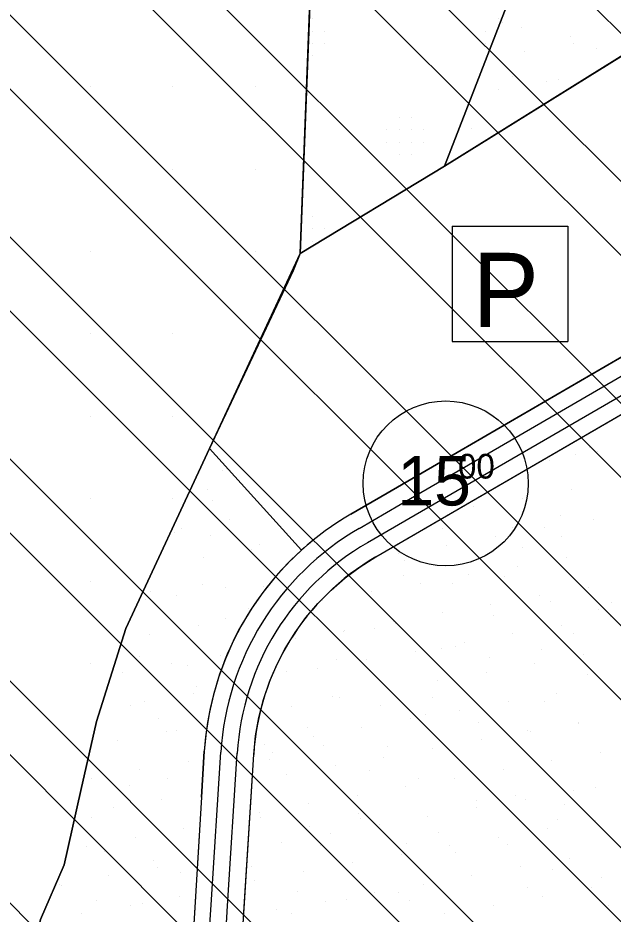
# Model space of a CAD drawing. Extents: x 419109 to 421295, y 4452223 to 4457798.
# Drawn here: x 420492.5 to 420672.9, y 4455694.4 to 4455966.2 of the extents above; entities that cross this region are included whole.
import ezdxf

# ---------------------------------------------------------------- set-up
doc = ezdxf.new("R2010")
doc.units = 0
for name, color, linetype in [('ADAKENARI', 7, 'Continuous'), ('KALDIRIM_FAT', 7, 'Continuous'), ('KD_DAIRE', 7, 'Continuous'), ('KD_YGEN', 7, 'Continuous'), ('PL_AYA_FUAR', 7, 'Continuous'), ('PL_AYA_PARK_DINLENME', 7, 'Continuous'), ('PL_KAMU_HİZMET_ALANI', 7, 'Continuous'), ('PL_T_TURIZM_TA', 7, 'Continuous'), ('PL_TA_K_OTOPARK', 7, 'Continuous'), ('SEMBOL_FAT', 7, 'Continuous'), ('SN_TR_SIVILASMA', 7, 'Continuous'), ('TRFAT_KHA', 7, 'Continuous'), ('TRFAT_PARKALANI', 7, 'Continuous'), ('TRFAT_TURİZM', 7, 'Continuous')]:
    doc.layers.add(name, color=color, linetype=linetype)

msp = doc.modelspace()

# ---------------------------------------------------------------- linework, layer by layer
at = {"layer": 'ADAKENARI'}
for p, q in [((420582.08, 4456000.28), (420578.04, 4455894.75)), ((420641.86, 4455973.2), (420621.81, 4455921.26)), ((420621.81, 4455921.26), (420693.23, 4455965.73)), ((420621.81, 4455921.26), (420578.04, 4455894.75)), ((420550.56, 4455835.6), (420578.04, 4455894.75)), ((420604.42, 4455822.11), (420705.46, 4455880.83)), ((420636.29, 4455823.29), (420701.58, 4455861.23)), ((420525.22, 4455781.05), (420550.56, 4455835.6)), ((420550.56, 4455835.6), (420578.39, 4455804.76)), ((420593.39, 4455815.7), (420604.42, 4455822.11)), ((420600.93, 4455802.74), (420636.29, 4455823.29)), ((420516.32, 4455752.85), (420525.22, 4455781.05)), ((420511.56, 4455731.89), (420516.32, 4455752.85)), ((420548.08, 4455729.82), (420548.96, 4455743.78)), ((420561.03, 4455696.59), (420563.93, 4455742.84)), ((420511.56, 4455731.89), (420506.44, 4455709.38)), ((420548.08, 4455729.82), (420544.57, 4455671.28)), ((420506.44, 4455709.38), (420499.28, 4455692.79)), ((420545.42, 4455447.04), (420561.03, 4455696.59))]:
    msp.add_line(p, q, dxfattribs=at)
for radius, start, end in [(89.66, 120.1641, 132.0545), (89.66, 132.0545, 176.4189), (74.66, 120.1641, 176.4189)]:
    msp.add_arc((420638.45, 4455738.18), radius, start, end, dxfattribs=at)
at = {"layer": 'KALDIRIM_FAT'}
for p, q in [((420608.38, 4455818.63), (420728.5, 4455888.44)), ((420612.88, 4455815.46), (420730.07, 4455883.57)), ((420595.91, 4455811.38), (420608.38, 4455818.63)), ((420598.42, 4455807.06), (420612.88, 4455815.46)), ((420551.05, 4455697.22), (420553.95, 4455743.47)), ((420556.04, 4455696.9), (420558.94, 4455743.16)), ((420535.52, 4455449.05), (420551.05, 4455697.22)), ((420540.51, 4455448.74), (420556.04, 4455696.9))]:
    msp.add_line(p, q, dxfattribs=at)
for radius in [84.66, 79.66]:
    msp.add_arc((420638.45, 4455738.18), radius, 120.1641, 176.4189, dxfattribs=at)
at = {"layer": 'KD_DAIRE'}
msp.add_circle((420622.14, 4455825.04), 25, dxfattribs=at)
at = {"layer": 'PL_AYA_FUAR'}
msp.add_lwpolyline([(420545.42, 4455447.04), (420563.93, 4455742.84), (420564.49, 4455748.45), (420565.48, 4455754), (420566.88, 4455759.47), (420568.69, 4455764.8), (420570.9, 4455769.99), (420573.49, 4455775), (420576.46, 4455779.79), (420579.77, 4455784.35), (420583.42, 4455788.65), (420587.39, 4455792.66), (420591.64, 4455796.35), (420596.17, 4455799.72), (420600.93, 4455802.74), (420701.58, 4455861.23), (420708.62, 4455863.92), (420715.79, 4455864.57), (420723.78, 4455862.78), (420730.13, 4455859.19), (420735, 4455853.4), (420771.9, 4455797.51), (420787.06, 4455778.4), (420884.04, 4455668.02)], dxfattribs=at)
at = {"layer": 'PL_AYA_PARK_DINLENME'}
for points in [[(420693.23, 4455965.73), (420621.81, 4455921.26), (420641.86, 4455973.2), (420672.86, 4455995.01), (420663.72, 4456014.91), (420665.12, 4456014.82), (420667.87, 4456014.43), (420670.53, 4456013.64), (420673.05, 4456012.46), (420675.36, 4456010.92), (420677.41, 4456009.05), (420679.17, 4456006.9), (420680.58, 4456004.51), (420681.62, 4456001.94)], [(420516.32, 4455752.85), (420525.22, 4455781.05), (420550.56, 4455835.6), (420578.39, 4455804.76), (420574.22, 4455800.75), (420570.32, 4455796.47), (420566.7, 4455791.96), (420563.38, 4455787.22), (420560.38, 4455782.28), (420557.7, 4455777.15), (420555.35, 4455771.87), (420553.35, 4455766.44), (420551.71, 4455760.89), (420550.42, 4455755.25), (420549.51, 4455749.54), (420548.96, 4455743.78), (420548.08, 4455729.82), (420544.57, 4455671.28), (420495.57, 4455677.66), (420499.28, 4455692.79), (420506.44, 4455709.38), (420511.56, 4455731.89)]]:
    msp.add_lwpolyline(points, close=True, dxfattribs=at)
at = {"layer": 'PL_KAMU_HİZMET_ALANI'}
msp.add_lwpolyline([(420582.08, 4456000.28), (420578.04, 4455894.75), (420575.94, 4455889.49), (420550.56, 4455835.6), (420525.22, 4455781.05), (420516.32, 4455752.85), (420511.56, 4455731.89), (420506.44, 4455709.38), (420499.28, 4455692.79), (420495.57, 4455677.66), (420488.85, 4455650.29), (420482.66, 4455589.65), (420479.31, 4455554.16), (420467.35, 4455501.65), (420461.1, 4455474.22), (420459.55, 4455467.41), (420458.85, 4455454.77), (420457.92, 4455437.99), (420419.68, 4455375.72), (420397.16, 4455340.76)], dxfattribs=at)
at = {"layer": 'PL_T_TURIZM_TA'}
msp.add_lwpolyline([(420641.86, 4455973.2), (420621.81, 4455921.26), (420578.04, 4455894.75), (420582.08, 4456000.28), (420584.65, 4456067.45), (420609.47, 4456053.71), (420608.68, 4456034.54), (420609.89, 4456031.03), (420610.86, 4456028.17), (420613.42, 4456024.49), (420615.55, 4456021.97), (420622.76, 4456017.94), (420626.27, 4456017.35), (420663.72, 4456014.91), (420672.86, 4455995.01)], close=True, dxfattribs=at)
at = {"layer": 'PL_TA_K_OTOPARK'}
msp.add_lwpolyline([(420578.04, 4455894.75), (420621.81, 4455921.26), (420693.23, 4455965.73), (420713.63, 4455902.08), (420714.27, 4455899.43), (420714.5, 4455896.71), (420714.32, 4455893.98), (420713.73, 4455891.31), (420712.75, 4455888.76), (420711.4, 4455886.39), (420709.7, 4455884.25), (420707.71, 4455882.38), (420705.46, 4455880.83), (420604.42, 4455822.11), (420593.39, 4455815.7), (420591.4, 4455814.51), (420589.43, 4455813.26), (420587.5, 4455811.97), (420585.61, 4455810.62), (420583.75, 4455809.23), (420581.92, 4455807.78), (420580.13, 4455806.29), (420578.39, 4455804.76), (420550.56, 4455835.6)], close=True, dxfattribs=at)
at = {"layer": 'SEMBOL_FAT'}
for p, q in [((420624.12, 4455903.06), (420624.12, 4455868.06)), ((420624.12, 4455903.06), (420659.12, 4455903.06)), ((420659.12, 4455903.06), (420659.12, 4455868.06)), ((420624.12, 4455868.06), (420659.12, 4455868.06))]:
    msp.add_line(p, q, dxfattribs=at)
at = {"layer": 'SN_TR_SIVILASMA'}
for p, q in [((421270.24, 4455366.53), (420198.6, 4456438.16)), ((421269.77, 4455322.09), (420183.63, 4456408.23)), ((421269.54, 4455299.87), (420176.15, 4456393.26)), ((421269.08, 4455255.43), (420161.18, 4456363.33)), ((421268.85, 4455233.21), (420151.38, 4456350.68)), ((421268.38, 4455188.77), (420123.47, 4456333.68)), ((421268.15, 4455166.56), (420116.87, 4456317.84)), ((421267.69, 4455122.12), (420103.66, 4456286.14)), ((421267.46, 4455099.9), (420097.06, 4456270.29)), ((421266.99, 4455055.46), (420083.86, 4456238.6)), ((421266.76, 4455033.24), (420079.94, 4456220.06)), ((421255.58, 4454999.52), (420079.94, 4456175.16)), ((421232.89, 4454999.76), (420079.94, 4456152.71)), ((421187.51, 4455000.24), (420079.94, 4456107.81))]:
    msp.add_line(p, q, dxfattribs=at)
at = {"layer": 'TRFAT_KHA'}
for p, q in [((420514.37, 4455945.38), (420514.37, 4455945.38)), ((420539.37, 4455945.38), (420539.37, 4455945.38)), ((420564.37, 4455945.38), (420564.37, 4455945.38)), ((420514.37, 4455920.38), (420514.37, 4455920.38)), ((420539.37, 4455920.38), (420539.37, 4455920.38)), ((420564.37, 4455920.38), (420564.37, 4455920.38)), ((420514.37, 4455895.38), (420514.37, 4455895.38)), ((420539.37, 4455895.38), (420539.37, 4455895.38)), ((420564.37, 4455895.38), (420564.37, 4455895.38)), ((420514.37, 4455870.38), (420514.37, 4455870.38)), ((420539.37, 4455870.38), (420539.37, 4455870.38)), ((420564.37, 4455870.38), (420564.37, 4455870.38)), ((420514.37, 4455845.38), (420514.37, 4455845.38)), ((420539.37, 4455845.38), (420539.37, 4455845.38)), ((420514.37, 4455820.38), (420514.37, 4455820.38)), ((420539.37, 4455820.38), (420539.37, 4455820.38)), ((420514.37, 4455795.38), (420514.37, 4455795.38)), ((420514.37, 4455770.38), (420514.37, 4455770.38)), ((420514.37, 4455745.38), (420514.37, 4455745.38))]:
    msp.add_line(p, q, dxfattribs=at)
at = {"layer": 'TRFAT_PARKALANI'}
for p, q in [((420639.48, 4455964.99), (420639.48, 4455964.99)), ((420645.06, 4455963.35), (420645.06, 4455963.35)), ((420659.83, 4455960.75), (420659.83, 4455960.75)), ((420660.92, 4455958.62), (420660.92, 4455958.62)), ((420646.14, 4455956.01), (420646.14, 4455956.01)), ((420667.85, 4455957.1), (420667.85, 4455957.1)), ((420642.45, 4455948.58), (420642.45, 4455948.58)), ((420652.81, 4455947.03), (420652.81, 4455947.03)), ((420656.36, 4455947.46), (420656.36, 4455947.46)), ((420638.03, 4455944.43), (420638.03, 4455944.43)), ((420629.92, 4455932.84), (420629.92, 4455932.84)), ((420665.77, 4455835.78), (420665.77, 4455835.78)), ((420661.59, 4455833.68), (420661.59, 4455833.68)), ((420668.28, 4455834.71), (420668.28, 4455834.71)), ((420653.51, 4455832.11), (420653.51, 4455832.11)), ((420554.42, 4455828.95), (420554.42, 4455828.95)), ((420550.04, 4455823.05), (420550.04, 4455823.05)), ((420660.17, 4455823.13), (420660.17, 4455823.13)), ((420551.47, 4455819.83), (420551.47, 4455819.83)), ((420645.4, 4455820.52), (420645.4, 4455820.52)), ((420630.62, 4455817.92), (420630.62, 4455817.92)), ((420556.7, 4455814.07), (420556.7, 4455814.07)), ((420656.87, 4455815.26), (420656.87, 4455815.26)), ((420666.83, 4455814.15), (420666.83, 4455814.15)), ((420541.93, 4455811.46), (420541.93, 4455811.46)), ((420621.04, 4455811.3), (420621.04, 4455811.3)), ((420642.47, 4455811.66), (420642.47, 4455811.66)), ((420652.06, 4455811.54), (420652.06, 4455811.54)), ((420539.98, 4455810.19), (420539.98, 4455810.19)), ((420550.95, 4455809.25), (420550.95, 4455809.25)), ((420637.29, 4455808.94), (420637.29, 4455808.94)), ((420657.25, 4455809.06), (420657.25, 4455809.06)), ((420565.72, 4455806.65), (420565.72, 4455806.65)), ((420622.51, 4455806.33), (420622.51, 4455806.33)), ((420645.38, 4455805.62), (420645.38, 4455805.62)), ((420548.59, 4455802.48), (420548.59, 4455802.48)), ((420563.36, 4455805.09), (420563.36, 4455805.09)), ((420607.74, 4455803.73), (420607.74, 4455803.73)), ((420658.72, 4455802.56), (420658.72, 4455802.56)), ((420609.54, 4455801.65), (420609.54, 4455801.65)), ((420643.95, 4455799.96), (420643.95, 4455799.96)), ((420609.46, 4455797.17), (420609.46, 4455797.17)), ((420629.17, 4455797.35), (420629.17, 4455797.35)), ((420548.35, 4455794.48), (420548.35, 4455794.48)), ((420570.02, 4455796.11), (420570.02, 4455796.11)), ((420614.4, 4455794.75), (420614.4, 4455794.75)), ((420624.23, 4455794.57), (420624.23, 4455794.57)), ((420639.87, 4455796.89), (420639.87, 4455796.89)), ((420532.7, 4455792.16), (420532.7, 4455792.16)), ((420555.25, 4455793.5), (420555.25, 4455793.5)), ((420566.92, 4455793.63), (420566.92, 4455793.63)), ((420599.63, 4455792.14), (420599.63, 4455792.14)), ((420665.38, 4455793.58), (420665.38, 4455793.58)), ((420531.08, 4455789.67), (420531.08, 4455789.67)), ((420540.48, 4455790.9), (420540.48, 4455790.9)), ((420584.86, 4455789.54), (420584.86, 4455789.54)), ((420650.61, 4455790.98), (420650.61, 4455790.98)), ((420653.77, 4455789.36), (420653.77, 4455789.36)), ((420672.33, 4455789.06), (420672.33, 4455789.06)), ((420562.25, 4455786.95), (420562.25, 4455786.95)), ((420635.83, 4455788.37), (420635.83, 4455788.37)), ((420668.55, 4455786.76), (420668.55, 4455786.76)), ((420555.43, 4455783.99), (420555.43, 4455783.99)), ((420621.06, 4455785.77), (420621.06, 4455785.77)), ((420636.49, 4455785.1), (420636.49, 4455785.1)), ((420672.04, 4455784.6), (420672.04, 4455784.6)), ((420547.14, 4455781.92), (420547.14, 4455781.92)), ((420600.65, 4455781.14), (420600.65, 4455781.14)), ((420606.29, 4455783.16), (420606.29, 4455783.16)), ((420606.85, 4455782.4), (420606.85, 4455782.4)), ((420657.27, 4455782), (420657.27, 4455782)), ((420532.37, 4455779.31), (420532.37, 4455779.31)), ((420576.75, 4455777.95), (420576.75, 4455777.95)), ((420591.21, 4455780.08), (420591.21, 4455780.08)), ((420591.52, 4455780.56), (420591.52, 4455780.56)), ((420642.49, 4455779.39), (420642.49, 4455779.39)), ((420660.84, 4455779.42), (420660.84, 4455779.42)), ((420625, 4455775.46), (420625, 4455775.46)), ((420627.72, 4455776.79), (420627.72, 4455776.79)), ((420553.8, 4455772.94), (420553.8, 4455772.94)), ((420612.95, 4455774.18), (420612.95, 4455774.18)), ((420620.76, 4455774.87), (420620.76, 4455774.87)), ((420651.17, 4455774.59), (420651.17, 4455774.59)), ((420663.93, 4455773.02), (420663.93, 4455773.02)), ((420529.23, 4455772.46), (420529.23, 4455772.46)), ((420539.03, 4455770.33), (420539.03, 4455770.33)), ((420544, 4455769.86), (420544, 4455769.86)), ((420589.16, 4455771.5), (420589.16, 4455771.5)), ((420598.18, 4455771.58), (420598.18, 4455771.58)), ((420635.53, 4455772.27), (420635.53, 4455772.27)), ((420649.15, 4455770.41), (420649.15, 4455770.41)), ((420524.26, 4455767.73), (420524.26, 4455767.73)), ((420573.84, 4455767.92), (420573.84, 4455767.92)), ((420583.41, 4455768.98), (420583.41, 4455768.98)), ((420634.38, 4455767.81), (420634.38, 4455767.81)), ((420619.61, 4455765.2), (420619.61, 4455765.2)), ((420665.07, 4455767.06), (420665.07, 4455767.06)), ((420546.54, 4455763.47), (420546.54, 4455763.47)), ((420604.84, 4455762.6), (420604.84, 4455762.6)), ((420670.59, 4455764.04), (420670.59, 4455764.04)), ((420545.69, 4455761.36), (420545.69, 4455761.36)), ((420587.74, 4455760.39), (420587.74, 4455760.39)), ((420590.07, 4455760), (420590.07, 4455760)), ((420618.15, 4455760.1), (420618.15, 4455760.1)), ((420655.82, 4455761.43), (420655.82, 4455761.43)), ((420526.63, 4455757.69), (420526.63, 4455757.69)), ((420530.92, 4455758.75), (420530.92, 4455758.75)), ((420575.29, 4455757.39), (420575.29, 4455757.39)), ((420602.51, 4455757.78), (420602.51, 4455757.78)), ((420626.27, 4455756.22), (420626.27, 4455756.22)), ((420641.04, 4455758.83), (420641.04, 4455758.83)), ((420651.94, 4455758.91), (420651.94, 4455758.91)), ((420535.04, 4455753.83), (420535.04, 4455753.83)), ((420611.5, 4455753.62), (420611.5, 4455753.62)), ((420616.11, 4455754.94), (420616.11, 4455754.94)), ((420580.27, 4455750.98), (420580.27, 4455750.98)), ((420596.73, 4455751.02), (420596.73, 4455751.02)), ((420632.06, 4455752.57), (420632.06, 4455752.57)), ((420662.47, 4455752.29), (420662.47, 4455752.29)), ((420662.48, 4455752.45), (420662.48, 4455752.45)), ((420537.58, 4455749.77), (420537.58, 4455749.77)), ((420540.53, 4455750.16), (420540.53, 4455750.16)), ((420581.95, 4455748.41), (420581.95, 4455748.41)), ((420640.45, 4455749.26), (420640.45, 4455749.26)), ((420646.83, 4455749.97), (420646.83, 4455749.97)), ((420647.7, 4455749.85), (420647.7, 4455749.85)), ((420522.8, 4455747.17), (420522.8, 4455747.17)), ((420567.18, 4455745.81), (420567.18, 4455745.81)), ((420585.13, 4455745.61), (420585.13, 4455745.61)), ((420632.93, 4455747.24), (420632.93, 4455747.24)), ((420569.49, 4455743.3), (420569.49, 4455743.3)), ((420604.61, 4455745.3), (420604.61, 4455745.3)), ((420618.16, 4455744.64), (420618.16, 4455744.64)), ((420669.14, 4455743.47), (420669.14, 4455743.47)), ((420544.24, 4455740.79), (420544.24, 4455740.79)), ((420568.78, 4455741.34), (420568.78, 4455741.34)), ((420603.39, 4455742.04), (420603.39, 4455742.04)), ((420654.36, 4455740.87), (420654.36, 4455740.87)), ((420529.47, 4455738.19), (420529.47, 4455738.19)), ((420588.62, 4455739.43), (420588.62, 4455739.43)), ((420599.04, 4455738.09), (420599.04, 4455738.09)), ((420629.45, 4455737.8), (420629.45, 4455737.8)), ((420639.59, 4455738.27), (420639.59, 4455738.27)), ((420514.69, 4455735.58), (420514.69, 4455735.58)), ((420537.93, 4455735.39), (420537.93, 4455735.39)), ((420573.84, 4455736.83), (420573.84, 4455736.83)), ((420613.81, 4455735.48), (420613.81, 4455735.48)), ((420624.82, 4455735.66), (420624.82, 4455735.66)), ((420522.29, 4455733.07), (420522.29, 4455733.07)), ((420526.15, 4455733.32), (420526.15, 4455733.32)), ((420610.05, 4455733.06), (420610.05, 4455733.06)), ((420661.02, 4455731.89), (420661.02, 4455731.89)), ((420667.4, 4455732.71), (420667.4, 4455732.71)), ((420536.13, 4455729.21), (420536.13, 4455729.21)), ((420595.28, 4455730.45), (420595.28, 4455730.45)), ((420643.35, 4455730.27), (420643.35, 4455730.27)), ((420646.25, 4455729.29), (420646.25, 4455729.29)), ((420521.35, 4455726.6), (420521.35, 4455726.6)), ((420580.5, 4455727.85), (420580.5, 4455727.85)), ((420631.48, 4455726.68), (420631.48, 4455726.68)), ((420631.56, 4455728.75), (420631.56, 4455728.75)), ((420658.13, 4455727.67), (420658.13, 4455727.67)), ((420514.66, 4455723.67), (420514.66, 4455723.67)), ((420565.73, 4455725.24), (420565.73, 4455725.24)), ((420566.02, 4455723.6), (420566.02, 4455723.6)), ((420595.72, 4455724.79), (420595.72, 4455724.79)), ((420616.71, 4455724.08), (420616.71, 4455724.08)), ((420580.79, 4455720.99), (420580.79, 4455720.99)), ((420596.43, 4455723.31), (420596.43, 4455723.31)), ((420601.94, 4455721.47), (420601.94, 4455721.47)), ((420655.91, 4455723.07), (420655.91, 4455723.07)), ((420667.69, 4455722.91), (420667.69, 4455722.91)), ((420542.79, 4455720.23), (420542.79, 4455720.23)), ((420587.16, 4455718.87), (420587.16, 4455718.87)), ((420620.07, 4455719.11), (420620.07, 4455719.11)), ((420652.91, 4455720.31), (420652.91, 4455720.31)), ((420528.01, 4455717.62), (420528.01, 4455717.62)), ((420572.39, 4455716.26), (420572.39, 4455716.26)), ((420610.34, 4455715.79), (420610.34, 4455715.79)), ((420638.14, 4455717.7), (420638.14, 4455717.7)), ((420640.75, 4455715.5), (420640.75, 4455715.5)), ((420513.24, 4455715.02), (420513.24, 4455715.02)), ((420518.81, 4455713.37), (420518.81, 4455713.37)), ((420584.23, 4455715.14), (420584.23, 4455715.14)), ((420623.37, 4455715.1), (420623.37, 4455715.1)), ((420625.11, 4455713.18), (420625.11, 4455713.18)), ((420533.59, 4455710.77), (420533.59, 4455710.77)), ((420608.6, 4455712.49), (420608.6, 4455712.49)), ((420659.57, 4455711.33), (420659.57, 4455711.33)), ((420534.67, 4455708.64), (420534.67, 4455708.64)), ((420563.42, 4455708.83), (420563.42, 4455708.83)), ((420579.05, 4455707.28), (420579.05, 4455707.28)), ((420593.82, 4455709.89), (420593.82, 4455709.89)), ((420644.8, 4455708.72), (420644.8, 4455708.72)), ((420654.65, 4455707.97), (420654.65, 4455707.97)), ((420519.9, 4455706.04), (420519.9, 4455706.04)), ((420541.61, 4455707.12), (420541.61, 4455707.12)), ((420564.28, 4455704.68), (420564.28, 4455704.68)), ((420630.03, 4455706.12), (420630.03, 4455706.12)), ((420669.43, 4455705.37), (420669.43, 4455705.37)), ((420505.13, 4455703.43), (420505.13, 4455703.43)), ((420505.77, 4455703.16), (420505.77, 4455703.16)), ((420615.26, 4455703.51), (420615.26, 4455703.51)), ((420647.01, 4455702.55), (420647.01, 4455702.55)), ((420666.23, 4455702.35), (420666.23, 4455702.35)), ((420541.34, 4455699.66), (420541.34, 4455699.66)), ((420577.32, 4455701.3), (420577.32, 4455701.3)), ((420600.49, 4455700.91), (420600.49, 4455700.91)), ((420607.73, 4455701.01), (420607.73, 4455701.01)), ((420651.46, 4455699.74), (420651.46, 4455699.74)), ((420516.21, 4455698.6), (420516.21, 4455698.6)), ((420526.56, 4455697.06), (420526.56, 4455697.06)), ((420530.11, 4455697.48), (420530.11, 4455697.48)), ((420585.71, 4455698.3), (420585.71, 4455698.3)), ((420592.09, 4455698.69), (420592.09, 4455698.69)), ((420611.18, 4455698.59), (420611.18, 4455698.59)), ((420636.69, 4455697.14), (420636.69, 4455697.14)), ((420671.36, 4455696.87), (420671.36, 4455696.87)), ((420511.79, 4455694.45), (420511.79, 4455694.45)), ((420570.94, 4455695.7), (420570.94, 4455695.7)), ((420575.34, 4455694.63), (420575.34, 4455694.63)), ((420621.92, 4455694.53), (420621.92, 4455694.53))]:
    msp.add_line(p, q, dxfattribs=at)
at = {"layer": 'TRFAT_TURİZM'}
for p, q in [((420581.79, 4455966), (420581.79, 4455966)), ((420638.04, 4455966), (420638.04, 4455966)), ((420581.79, 4455962.25), (420581.79, 4455962.25)), ((420585.54, 4455962.25), (420585.54, 4455962.25)), ((420634.29, 4455962.25), (420634.29, 4455962.25)), ((420581.79, 4455958.5), (420581.79, 4455958.5)), ((420585.54, 4455958.5), (420585.54, 4455958.5)), ((420634.29, 4455958.5), (420634.29, 4455958.5)), ((420581.79, 4455954.75), (420581.79, 4455954.75)), ((420608.04, 4455936), (420608.04, 4455936)), ((420611.79, 4455936), (420611.79, 4455936)), ((420604.29, 4455932.25), (420604.29, 4455932.25)), ((420608.04, 4455932.25), (420608.04, 4455932.25)), ((420611.79, 4455932.25), (420611.79, 4455932.25)), ((420615.54, 4455932.25), (420615.54, 4455932.25)), ((420604.29, 4455928.5), (420604.29, 4455928.5)), ((420608.04, 4455928.5), (420608.04, 4455928.5)), ((420611.79, 4455928.5), (420611.79, 4455928.5)), ((420615.54, 4455928.5), (420615.54, 4455928.5)), ((420608.04, 4455924.75), (420608.04, 4455924.75)), ((420611.79, 4455924.75), (420611.79, 4455924.75)), ((420581.79, 4455906), (420581.79, 4455906)), ((420581.79, 4455902.25), (420581.79, 4455902.25)), ((420585.54, 4455902.25), (420585.54, 4455902.25)), ((420581.79, 4455898.5), (420581.79, 4455898.5))]:
    msp.add_line(p, q, dxfattribs=at)

# ---------------------------------------------------------------- texts
at = {"layer": 'KD_YGEN'}
for s, height, p in [('15', 15, (420607.48, 4455818.34)), ('00', 7.5, (420625.88, 4455826.5))]:
    msp.add_text(s, height=height, dxfattribs=at).set_placement(p)
at = {"layer": 'SEMBOL_FAT'}
msp.add_text('P', height=22.5, dxfattribs=at).set_placement((420630.32, 4455872.48))

doc.saveas('drawing.dxf')
